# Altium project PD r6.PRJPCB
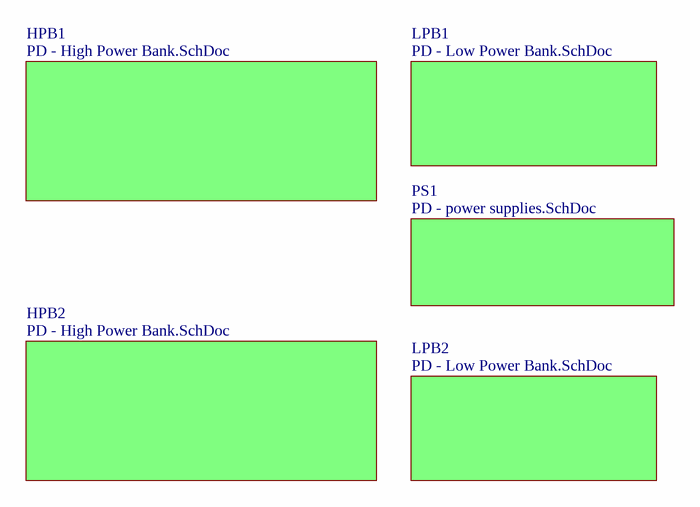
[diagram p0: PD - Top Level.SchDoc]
ProjectTitle: FRoSTY Power Distribution, Rev 6
8 sheets, 258 parts. Net scope: flat (ports and power ports of the same name join across sheets).
Board file: PD6.PcbDoc
Sheets:
  PD - Top Level.SchDoc
    PS1 = PD - power supplies.SchDoc
      U1000 = 24V_1.5A Supply.SchDoc
      U_5V_3A Supply = 5V_3A Supply.SchDoc
      U_12V_2A Supply = 12V_2A Supply.SchDoc
    HPB2 = PD - High Power Bank.SchDoc
    HPB1 = PD - High Power Bank.SchDoc
    LPB1 = PD - Low Power Bank.SchDoc
    LPB2 = PD - Low Power Bank.SchDoc
  Title.SchDoc

## Sheet PD - Top Level.SchDoc: Top Level
size Letter; DrawnBy: EJVW; Revision: 2

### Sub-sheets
HPB1 = PD - High Power Bank.SchDoc: no entries
HPB2 = PD - High Power Bank.SchDoc: no entries
LPB1 = PD - Low Power Bank.SchDoc: no entries
LPB2 = PD - Low Power Bank.SchDoc: no entries
PS1 = PD - power supplies.SchDoc: no entries

## Sheet PD - power supplies.SchDoc: Power Supplies
size Letter; DrawnBy: EJVW; DocumentNumber: 4; Revision: 4; SheetNumber: 3; SheetTotal: 6; PageSetup: Record=PageOptions|CenterHorizontal=True|CenterVertical=True|PrintScale=0.96|XCorrection=1.00|YCorrection=1.00|PrintKind=1|BorderSize=5000000|LeftOffset=0|BottomOffset=0|Orientation=2|PaperLength=1000|PaperWidth=1000|Scale=100|PaperSource=7|PrintQuality=-4|MediaType=1|DitherType=10|PaperKind=11x17|PrintScaleMode=1
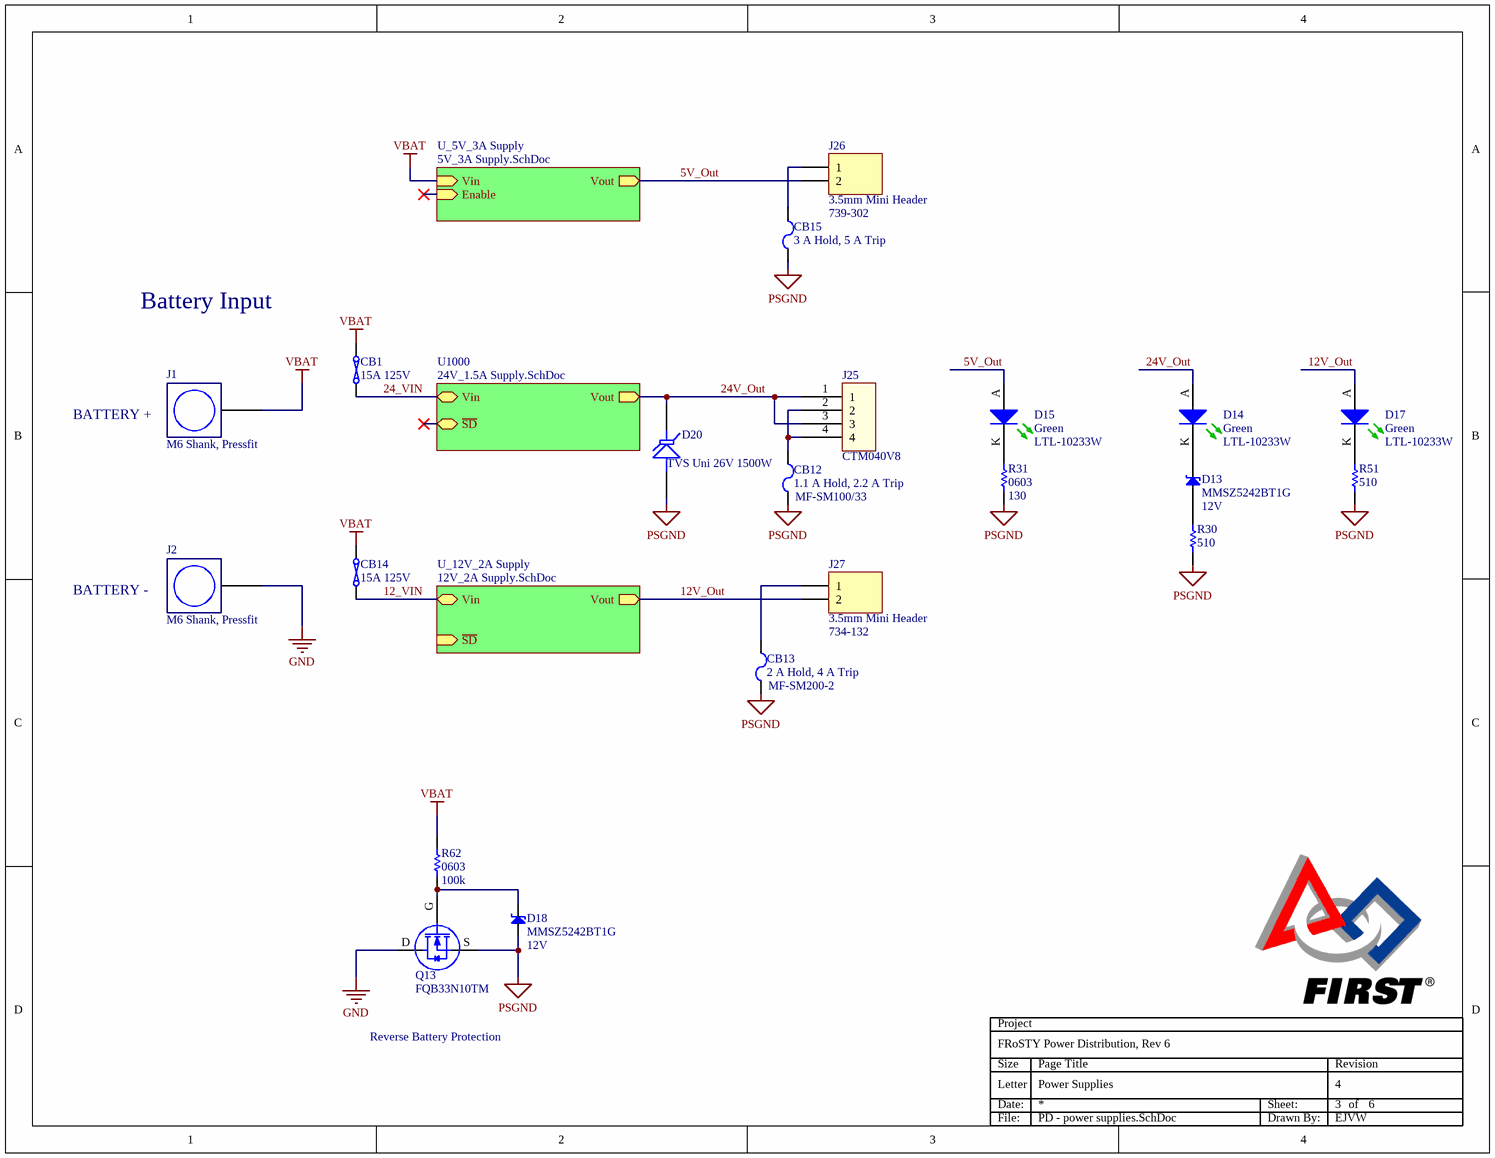
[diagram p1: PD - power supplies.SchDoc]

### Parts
(Parts that share a designator on the sheet are numbered #1, #2 ... from top to bottom, then left to right.)
CB1#1  15A 125V  [Fuse2410 - bel]
CB12#1  1.1 A Hold, 2.2 A Trip  [PTC-MF-SM-Small]
CB13#1  2 A Hold, 4 A Trip  [PTC-MF-SM-Large]
CB14#1  15A 125V  [Fuse2410 - bel]
CB15  3 A Hold, 5 A Trip  [2920L]
D13  MMSZ5242BT1G  value 12V  [SOD-123]
D14  Green  [T-1 3/4]
D15  Green  [T-1 3/4]
D17  Green  [T-1 3/4]
D18#1  MMSZ5242BT1G  value 12V  [SOD-123]
D20#1  TVS Uni 26V 1500W  [SMC]
J1#1  M6 Shank, Pressfit  [Wurth 7461098]
J2#1  M6 Shank, Pressfit  [Wurth 7461098]
J25  MFG_PN: CTM040V8  [Sauro CTM040V8]  (hidden comment: Sauro CTM040V8)
J26  3.5mm Mini Header  MFG_PN: 739-302  [WAGO 739-302]
J27  3.5mm Mini Header  MFG_PN: 734-132  [WAGO 734-132]
Q13  FQB33N10TM  [TO-263AB/D2PAK]
R30#1  value 510  [R1206_C]  (hidden comment: 510 ohm 1206 1%)
R31#1  value 130  Footprint: 0603  [R0603_C]  (hidden comment: 130 ohm 0603 1%)
R51#1  value 510  [R1206_C]  (hidden comment: 510 ohm 1206 1%)
R62#1  value 100k  Footprint: 0603  [R0603_C]  (hidden comment: 100k ohm 0603 1%)

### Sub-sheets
U1000 = 24V_1.5A Supply.SchDoc: Vout (out), ~{SD}, Vin
U_5V_3A Supply = 5V_3A Supply.SchDoc: Vin (in), Enable (in), Vout (out)
U_12V_2A Supply = 12V_2A Supply.SchDoc: Vout (out), ~{SD} (in), Vin

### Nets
GND: J2#1.PAD Q13.D
PSGND: CB12#1.1 CB13#1.1 CB15.1 D18#1.A D20#1.A Q13.S R30#1.1 R31#1.1 R51#1.1
VBAT: CB1#1.2 CB14#1.2 J1#1.PAD R62#1.2 ; sheet U_5V_3A Supply/Vin
5V_Out: D15.A J26.2 ; sheet U_5V_3A Supply/Vout
12_VIN: CB14#1.1 ; sheet U_12V_2A Supply/Vin
12V_Out: D17.A J27.2 ; sheet U_12V_2A Supply/Vout
24_VIN: CB1#1.1 ; sheet U1000/Vin
24V_Out: D14.A D20#1.K J25.1 J25.3 ; sheet U1000/Vout
NetCB12#1_2: CB12#1.2 J25.2 J25.4
NetCB13#1_2: CB13#1.2 J27.1
NetCB15_2: CB15.2 J26.1
NetD13_A: D13.A R30#1.2
NetD13_K: D13.K D14.K
NetD15_K: D15.K R31#1.2
NetD17_K: D17.K R51#1.2
NetD18#1_K: D18#1.K Q13.G R62#1.1

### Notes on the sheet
- Battery Input
- BATTERY +
- BATTERY -
- Reverse Battery Protection

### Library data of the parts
CB1#1 CB14#1 = Fuse SSQ 15: FUSE 12A 125V 6125 FAST SSQ; MFG: Bel Fuse Inc; MFG_PN: SSQ 15; DIST: DigiKey; DIST_PN: 507-1059-1-ND; R_min: 4; I trip (A): 15; Time to Trip: 10s @ 25A; V Max: 125; Cost (1000): 0.22400; Cost (MOQ): 0.76000
CB12#1 = MF-SM100/33: PTC 1.1A / 2.2A SMT; MFG: Bourns Inc.; DIST: DigiKey; DIST_PN: MF-SM100/33-2CT-ND; R_min: 120 mOhms; I hold (A): 2.2; I trip (A): 1.1; R_max: 410 mOhms; Time to Trip: 5 s @ 8 A; V Max: 33 V; I max (A): 40; Cost (1000): 0.40
CB13#1 = MF-SM200-2: PTC 2A /  4A SMT; MFG: Bourns Inc.; DIST: DigiKey; DIST_PN: MF-SM200CT-ND; R_min: 45; I hold (A): 2; I trip (A): 4; R_max: 125; Time to Trip: 12 s @ 8 A; V Max: 15; I max (A): 100; Cost (1000): 0.44650; Cost (MOQ): 0.67000
CB15 = 2920L300/15DR: PTC 3A /  5A SMT2920; MFG: LITTELFUSE; DIST: Newark; DIST_PN: 05M2801; R_min: 15 mOhms; I hold (A): 3.00; I trip (A): 5.00; R_max: 30 mOhms; Time to Trip: 10.3s @ 12.5A; V Max: 15; I max (A): 40.0; Cost (1000): 0.379; R post trip (1000): 48; Cost (MOQ): 0.500
D13 D18#1 = MMSZ5242BT1G_1: 12V 500mW Zener; MFG: ON Semiconductor; DIST: DIGIKEY; DIST_PN: MMSZ5242BT1GOSCT-ND; Checked: SCH 11/17/07
D14 D15 D17 = LTL-10233W: T-1 3/4 Green; DIST: DigiKey; DIST_PN: 160-1089-ND; MFG: LITE-ON INC; V_F: 2.1V; I_F: 20mA; Maximum Continuous Current: 30mA; Luminous Intensity: 40 mcd; Cost (1000): 0.04640; Cost (MOQ): 0.07300
D20#1 = SMCJ26A: Cost (1000): 0.32490; Cost (MOQ): 0.64000; DIST: DigiKey; DIST_PN: SMCJ26ALFCT-ND; MFG: Littelfuse Inc
J1#1 J2#1 = Wurth M6 PressFit Shank: MFG: Wurth Elektronik; MFG_PN: 7461098; Current Rating: 250 A; Cost (1000): 1.55; Cost (MOQ): 1.90
J25 = Sauro CTM040V8: 4 position, vertical locking connector with screw flanges, 3.5mm spacing; BOM Note: Specified by NI; Current Rating: 13.5; Engagement Force: 12 N (3 per Pole); Mates With: CTF04BV8-CN
J26 = WAGO 739-302: 3.5mm Terminal Strip, 14-28 AWG; MFG: WAGO; Current Rating: 6
J27 = WAGO 734-132: 3.5mm Header Protected against Mismating; MFG: WAGO; Checked: SCH 11/11/07; Current Rating: 10 A; Mates With: 734-102/037-000
Q13 = FQB33N10TM: N-CH 100V D2 33A; MFG: Fairchild; DIST: DigiKey; DIST_PN: FQB33N10TMCT-ND; R_DS: 52mOhms; V_DS: 100; V_GS: 25; R?JC: 50; Topology: N; Cost (1000): 0.48720; Cost (MOQ): 1.04000; Q_G (nC): 38; V_THRESH (Volts): 2 - - 4; ID @ TA = 25°C (Amps): 33; BOM Note: Or similar - VGS>=30V, I_D > 25 A
R30#1 R51#1 = 510 ohm 1206 1%: MFG: Rohm; MFG_PN: MCR18EZHF3300; DIST: DigiKey; DIST_PN: RHM510FRCT-ND; Power: 0.25W, 1/4W; Cost (1000): 0.02262
R31#1 = 130 ohm 0603 1%: MFG: Rohm; MFG_PN: MCR03EZPFX1300; DIST: DigiKey; DIST_PN: RHM130HCT-ND; Power: 0.1; BOM Note: Generic - May be replaced by equal or better part; Cost (1000): 0.01595; Cost (MOQ): 0.076
R62#1 = 100k ohm 0603 1%: MFG: Rohm; MFG_PN: MCR03EZPFX1003; DIST: DigiKey; DIST_PN: RHM100KHCT-ND; Power: 0.1; Cost (1000): 0.01595; Cost (MOQ): 0.076; BOM Note: Generic - May be replaced by equal or better part

## Sheet 24V_1.5A Supply.SchDoc: 24V 1A Boost Supply, 4.5-15V Input
size Letter; DrawnBy: EJVW; DocumentNumber: 6; Revision: 4; SheetNumber: 6; SheetTotal: 6
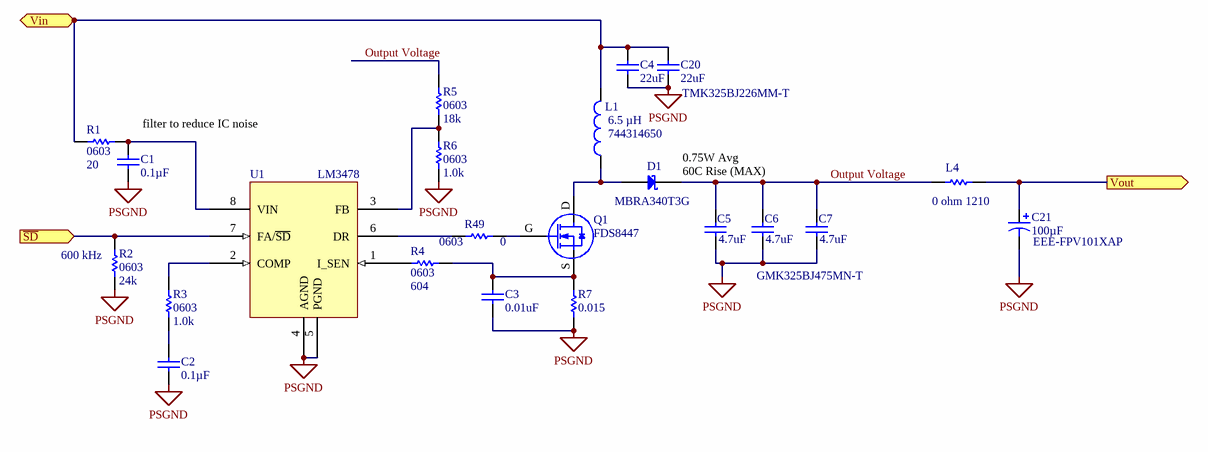
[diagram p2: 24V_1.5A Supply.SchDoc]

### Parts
(Parts that share a designator on the sheet are numbered #1, #2 ... from top to bottom, then left to right.)
C1  value 0.1µF  [C0805_C]  (hidden comment: 0.1uF 0805 Bypass)
C2  value 0.1µF  [C0805_C]  (hidden comment: 0.1uF 0805 Bypass)
C3  value 0.01uF  [C0603_C]  (hidden comment: 0.01uF 0603)
C4  value 22uF  [C1210_C]  (hidden comment: 22uF 1210 High I_RMS)
C5  value 4.7uF  [C1210_C]  (hidden comment: 4.7uF 1210 High I_RMS)
C6  value 4.7uF  [C1210_C]  (hidden comment: 4.7uF 1210 High I_RMS)
C7  value 4.7uF  MFG_PN: GMK325BJ475MN-T  [C1210_C]  (hidden comment: 4.7uF 1210 High I_RMS)
C20  value 22uF  MFG_PN: TMK325BJ226MM-T  [C1210_C]  (hidden comment: 22uF 1210 High I_RMS)
C21  value 100µF  MFG_PN: EEE-FPV101XAP  [SMT-CAN Panasonic D8]  (hidden comment: 100µF SMT - Panasonic)
D1#1  MBRA340T3G  [SMA]
L1  value 6.5 µH  MFG_PN: 744314650  [Wurth WE-HC 744314X]  (hidden comment: 4.7 µH 6 A)
L4  0 ohm 1210  [R1210_C]
Q1#1  FDS8447  [SO-8_M FET]
R1#1  value 20  Footprint: 0603  [R0603_C]  (hidden comment: 20 ohm 0603 1%)
R2#1  value 24k  Footprint: 0603  [R0603_C]  (hidden comment: 24k ohm 0603 1%)
R3#1  value 1.0k  Footprint: 0603  [R0603_C]  (hidden comment: 1.0k ohm 0603 1%)
R4#1  value 604  Footprint: 0603  [R0603_C]  (hidden comment: 604 ohm 0603 1%)
R5#1  value 18k  Footprint: 0603  [R0603_C]  (hidden comment: 18k ohm 0603 1%)
R6#1  value 1.0k  Footprint: 0603  [R0603_C]  (hidden comment: 1.0k ohm 0603 1%)
R7#1  value 0.015  [RL3720 - Susumu]  (hidden comment: 15 milliohm RL3720 2% 1W)
R49  value 0  Footprint: 0603  [R0603_C]  (hidden comment: 0 ohm 0603)
U1  LM3478  [MUA08A]

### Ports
Vin (in), Vout (out), ~{SD} (in)

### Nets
PSGND: C1.1 C2.1 C3.1 C4.1 C5.1 C6.1 C7.1 C20.1 C21.- R2#1.1 R6#1.1 R7#1.1 U1.4(AGND) U1.5(PGND)
Output Voltage: C5.2 C6.2 C7.2 D1#1.K L4.1 R5#1.2
NetC1_2: C1.2 R1#1.2 U1.8(VIN)
NetC2_2: C2.2 R3#1.1
NetC3_2: C3.2 Q1#1.S R4#1.2 R7#1.2
NetC4_2: C4.2 C20.2 L1.2 R1#1.1 ; port Vin
NetC11_2: C21.+ L4.2 ; port Vout
NetD1#1_A: D1#1.A L1.1 Q1#1.D
NetQ1#1_G: Q1#1.G R49.2
NetR2#1_2: R2#1.2 U1.7(FA/~{SD}) ; port ~{SD}
NetR3#1_2: R3#1.2 U1.2(COMP)
NetR4#1_1: R4#1.1 U1.1(I_SEN)
NetR5#1_1: R5#1.1 R6#1.2 U1.3(FB)
NetR49_1: R49.1 U1.6(DR)

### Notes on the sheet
- filter to reduce IC noise
- (near D1#1) 0.75W Avg
  60C Rise (MAX)
- (near R2#1) 600 kHz

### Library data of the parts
C1 C2 = 0.1uF 0805 Bypass: MFG: Kemet; MFG_PN: C0805C104K5RACTU; DIST: DigiKey; DIST_PN: 399-1170-1-ND; Tolerance: ±10%; Temperature Coefficient: X7R; Voltage: 50; Checked: SCH 3/2/2008; Cost (1000): 0.01260
C3 = 0.01 uF 0603 50V: MFG: Kemet; MFG_PN: C0603C103K5RACTU; DIST: DigiKey; DIST_PN: 399-1091-1-ND; Tolerance: ±10%; Temperature Coefficient: X7R; Voltage: 50V; Checked: SCH 3/2/2008; Cost (1000): 0.00520; Cost (MOQ): 0.02200
C4 = 22uF 1210 25V X5R: MFG: Taiyo Yuden; MFG_PN: TMK325BJ226MM-T; DIST: DigiKey; DIST_PN: 587-2086-1-ND; Tolerance: 20%; Voltage: 25; I_RMS@1000KHz Max: 4.4; I_RMS@10KHz Max: 2.6; ESR: .005; Cost (1000): 0.26600; Cost (MOQ): 1.62800
C5 C6 = 4.7uF 1210 High I_RMS: 4.7uF 1210 35V X5R; MFG: Taiyo Yuden; MFG_PN: GMK325BJ475MN-T; DIST: DigiKey; DIST_PN: 587-1781-1-ND; Tolerance: 20%; Voltage: 35; I_RMS@10KHz Max: 1.5A; I_RMS@100kHz Max: 3.5A
C7 = 4.7uF 1210 High I_RMS: 4.7uF 1210 35V X5R; MFG: Taiyo Yuden; DIST: DigiKey; DIST_PN: 587-1781-1-ND; Tolerance: 20%; Voltage: 35; I_RMS@10KHz Max: 1.5A; I_RMS@100kHz Max: 3.5A
C20 = 22uF 1210 25V X5R: MFG: Taiyo Yuden; DIST: DigiKey; DIST_PN: 587-2086-1-ND; Tolerance: 20%; Voltage: 25; I_RMS@1000KHz Max: 4.4; I_RMS@10KHz Max: 2.6; ESR: .005; Cost (1000): 0.26600; Cost (MOQ): 1.62800
C21 = 100µF 35V EEEFPV101XAP: 100µF 35V CAN-SMT; DIST: DigiKey; DIST_PN: PCE4554CT-ND; MFG: Panasonic - ECG; Tolerance: ±20%; Voltage: 35; Max Temperature: 105C; ESR: .160; Cost (1000): 0.36100; Cost (MOQ): 0.61400
D1#1 = MBRA340T3G: 3A Schottky Diode; DIST: DigiKey; DIST_PN: MBRA340T3GOSCT-ND; MFG: ON Semiconductor; Forward Voltage: 0.38; Surge Rating (8.3ms Half Sine): 100A; Voltage Rating: 40V
L1 = WE-HC 6.5-6: 6.5 µH 6 A 20% SMD; MFG: Wurth; DIST: DigiKey; DIST_PN: 732-1162-1-ND; Cost (1000): 1.10000; DCR (Ohms): .025; Cost (MOQ): 3.30000; IRMS (40C) A: 5.9; ISAT (10%)  A: 3; SRF (MHz): 50
L4 = 0 ohm 1210 5%: MFG: Vishay/Dale; MFG_PN: CRCW12100000Z0EA; DIST: DigiKey; DIST_PN: 541-0.0VCT-ND; Cost (1000): 0.05510; Cost (MOQ): 0.26100; Value: 0; Power: 0.333W, 1/3W
Q1#1 = FDS8447: N-CH 40V SO8 12.8A; MFG: Fairchild; DIST: DigiKey; DIST_PN: FDS8447CT-ND; Q_G (nC): 35; R_DS: 10.5mOhms; V_DS: 40; V_GS: 20; ID @ TA = 25°C (Amps): 12.8; R?JC: 50; Topology: N; V_THRESH (Volts): 1 - 1.8 - 3; Cost (1000): 0.41895
R1#1 = 20 ohm 0603 1%: MFG: Rohm; MFG_PN: MCR03EZPFX20R0; DIST: DigiKey; DIST_PN: RHM20.0HCT-ND; Power: 0.1; BOM Note: Generic - May be replaced by equal or better part; Cost (1000): 0.01595; Cost (MOQ): 0.076
R2#1 = 24k ohm 0603 1%: MFG: Rohm; MFG_PN: MCR03EZPFX2402; DIST: DigiKey; DIST_PN: RHM24.0KHCT-ND; Power: 0.1; BOM Note: Generic - May be replaced by equal or better part; Cost (1000): 0.01595; Cost (MOQ): 0.076
R3#1 R6#1 = 1.0k ohm 0603 1%: MFG: Rohm; MFG_PN: MCR03EZPFX1001; DIST: DigiKey; DIST_PN: RHM1.00KHCT-ND; Power: 0.1; BOM Note: Generic - May be replaced by equal or better part; Cost (1000): 0.01595; Cost (MOQ): 0.076
R4#1 = 604 ohm 0603 1%: MFG: Rohm; MFG_PN: MCR03EZPFX6040; DIST: DigiKey; DIST_PN: RHM604HCT-ND; Power: 0.1 W
R5#1 = 18k ohm 0603 1%: MFG: Rohm; MFG_PN: MCR03EZPFX1802; DIST: DigiKey; DIST_PN: RHM18.0KHCT-ND; Power: 0.1; BOM Note: Generic - May be replaced by equal or better part; Cost (1000): 0.01595; Cost (MOQ): 0.076
R7#1 = 15 milliohm RL3720 2% 1W: MFG: Susumu Co Ltd; MFG_PN: RL3720WT-R015-G; DIST: DigiKey; DIST_PN: RL37WT.015GCT-ND; Power: 0.5; Cost (1000): 0.348; Cost (MOQ): 1.65
R49 = 0 ohm 0603: MFG: Rohm; MFG_PN: MCR03EZPJ000; DIST: DigiKey; DIST_PN: RHM0.0GCT-ND; Power: 0.1; Cost (1000): 0.01595; Cost (MOQ): 0.076; BOM Note: Generic - May be replaced by equal or better part
U1 = LM3478: Low Side N Switcher Controller - Boost, Flyback, SEPIC; DIST: DigiKey; DIST_PN: LM3478MMCT-ND; MFG: National; MFG_PN: LM3478MM/NOPB; ADJ Pin Voltage: 1.26 V; Checked: SCH 3/2/2008; Current Limit: "10 A"; Driver Current Limit: 1 A; Max Voltage: 40 V; Quiescent Current: 2 mA; Shutdown Current: 2 uA; Voltage Output: Adj

## Sheet 5V_3A Supply.SchDoc: 5V 3A Buck Supply, 7-15V Input
size Letter; DrawnBy: EJVW; Revision: 1
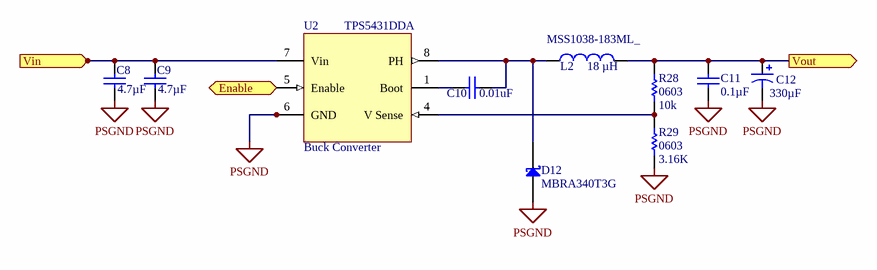
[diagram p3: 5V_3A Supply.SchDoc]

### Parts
(Parts that share a designator on the sheet are numbered #1, #2 ... from top to bottom, then left to right.)
C8  value 4.7µF  [C0805_C]  (hidden comment: 4.7uF 0805 25V X5R)
C9  value 4.7µF  [C0805_C]  (hidden comment: 4.7uF 0805 25V X5R)
C10  value 0.01uF  [C0603_C]  (hidden comment: 0.01uF 0603)
C11  value 0.1µF  [C0805_C]  (hidden comment: 0.1uF 0805 Bypass)
C12  value 330µF  [SMT-CAN Nippon F80]  (hidden comment: 330µF SMT - Chemi-Con)
D12  MBRA340T3G  [SMA]
L2  value 18 µH  [CoilCraft MSS1038]  (hidden comment: 18 µH 3.35A ±20% SMD)
R28#1  value 10k  Footprint: 0603  [R0603_C]  (hidden comment: 10k ohm 0603 1%)
R29#1  value 3.16K  Footprint: 0603  [R0603_C]  (hidden comment: 3.16k ohm 0603 1%)
U2  Buck Converter  MFG_PN: TPS5431DDA  [TPS543X]

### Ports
Enable (in), Vin (in), Vout (out)

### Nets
PSGND: C8.1 C9.1 C11.1 C12.- D12.A R29#1.1 U2.6(GND) U2.PAD
NetC4_2: C8.2 C9.2 U2.7(Vin) ; port Vin
NetC10_1: C10.1 U2.1(Boot)
NetC10_2: C10.2 D12.K L2.1 U2.8(PH)
NetC11_2: C11.2 C12.+ L2.2 R28#1.2 ; port Vout
NetR28#1_1: R28#1.1 R29#1.2 U2.4(V_Sense)
NetU2_5: U2.5(Enable) ; port Enable

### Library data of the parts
C8 C9 = 4.7uF 0805 25V X5R: CERAMIC 4.7uF 25V X5R 0805; MFG: Panasonic - ECG; MFG_PN: ECJ-2FB1E475M; DIST: DigiKey; DIST_PN: PCC2321CT-ND; Tolerance: ±20%; Checked: SCH 3/2/2008; Cost (1000): 0.08988
C10 = 0.01 uF 0603 50V: as C3 on sheet 24V_1.5A Supply
C11 = 0.1uF 0805 Bypass: as C1 on sheet 24V_1.5A Supply
C12 = 330µF 6.3V CAN-SMT: 330µF 6.3V ELECT CAN-SMT; DIST: DigiKey; DIST_PN: 565-2059-1-ND; MFG: United Chemi-Con; MFG_PN: EMVA6R3ADA331MF80G; Tolerance: ±20%; Checked: SCH 3/2/2008; Max Temperature: 85 C; Ripple Current: 0.135 A; Cost (1000): 0.10266
D12 = MBRA340T3G: as D1#1 on sheet 24V_1.5A Supply
L2 = MSS1038-183ML_: MFG: CoilCraft; DCR (Ohms): 0.065; IRMS (20C) A: 2.25; IRMS (40C) A: 3.35; ISAT (10%)  A: 2.44; ISAT (20%) A: 3.1; ISAT (30%) A: 3.52; SRF (MHz): 18; Cost (1000): 0.41
R28#1 = 10k ohm 0603 1%: MFG: Rohm; MFG_PN: MCR03EZPFX1002; DIST: DigiKey; DIST_PN: RHM10.0KHCT-ND; Power: 0.1; BOM Note: Generic - May be replaced by equal or better part; Cost (1000): 0.01595; Cost (MOQ): 0.076
R29#1 = 3.16k ohm 0603 1%: MFG: Rohm; MFG_PN: MCR03EZPFX3161; DIST: DigiKey; DIST_PN: RHM3.16KHCT-ND; Power: 0.1 W
U2 = TPS5431: 3-A, WIDE INPUT RANGE, STEP-DOWN SWIFT CONVERTER; ADJ Pin Voltage: 1.221; Checked: SCH 3/2/2008; Current Limit: 3; DIST: DigiKey; DIST_PN: 296-19662-5-ND; Max Voltage: 23; MFG: TI; Quiescent Current: 3 mA; Shutdown Current: 20 uA; Voltage Output: 1.22 +; Switch Frequency (kHz): 500; Cost (1000): 2.20; BOM Note: May be replaced by TPS5430

## Sheet 12V_2A Supply.SchDoc: 12V 2A Boost Supply, 4.5-12V Input
size Letter; DrawnBy: EJVW; DocumentNumber: 5; Revision: 2; SheetNumber: 5; SheetTotal: 6
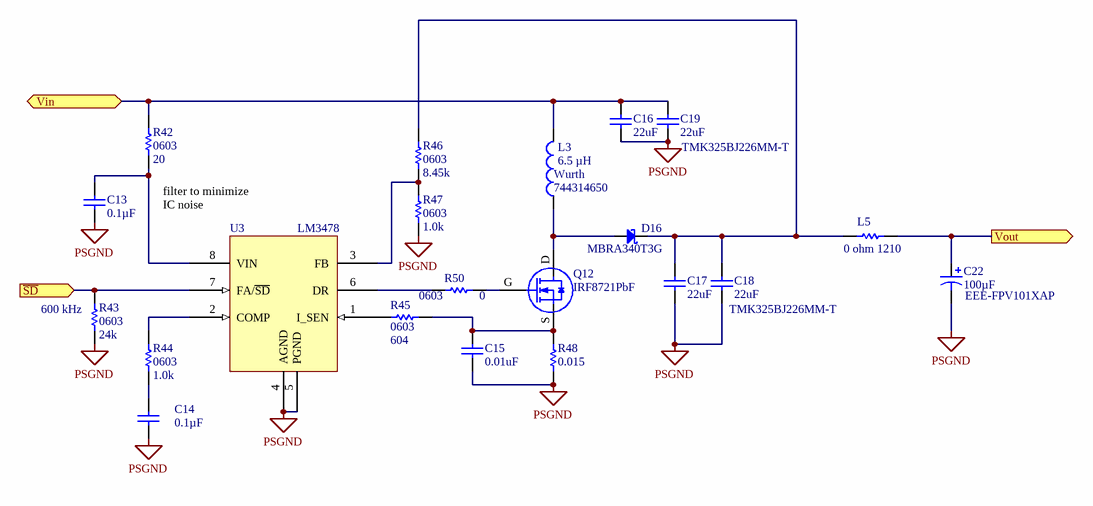
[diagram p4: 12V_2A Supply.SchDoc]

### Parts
C13  value 0.1µF  [C0805_C]  (hidden comment: 0.1uF 0805 Bypass)
C14  value 0.1µF  [C0805_C]  (hidden comment: 0.1uF 0805 Bypass)
C15  value 0.01uF  [C0603_C]  (hidden comment: 0.01uF 0603)
C16  value 22uF  [C1210_C]  (hidden comment: 22uF 1210 High I_RMS)
C17  value 22uF  [C1210_C]  (hidden comment: 22uF 1210 High I_RMS)
C18  value 22uF  MFG_PN: TMK325BJ226MM-T  [C1210_C]  (hidden comment: 22uF 1210 High I_RMS)
C19  value 22uF  MFG_PN: TMK325BJ226MM-T  [C1210_C]  (hidden comment: 22uF 1210 High I_RMS)
C22  value 100µF  MFG_PN: EEE-FPV101XAP  [SMT-CAN Panasonic D8]  (hidden comment: 100µF SMT - Panasonic)
D16  MBRA340T3G  [SMA]
L3  value 6.5 µH  MFG: Wurth  MFG_PN: 744314650  [Wurth WE-HC 744314X]  (hidden comment: 4.7 µH 6 A)
L5  0 ohm 1210  [R1210_C]
Q12  IRF8721PbF  [SO-8_M FET]
R42  value 20  Footprint: 0603  [R0603_C]  (hidden comment: 20 ohm 0603 1%)
R43  value 24k  Footprint: 0603  [R0603_C]  (hidden comment: 24k ohm 0603 1%)
R44  value 1.0k  Footprint: 0603  [R0603_C]  (hidden comment: 1.0k ohm 0603 1%)
R45  value 604  Footprint: 0603  [R0603_C]  (hidden comment: 604 ohm 0603 1%)
R46  value 8.45k  Footprint: 0603  [R0603_C]  (hidden comment: 8.45k ohm 0603 1%)
R47  value 1.0k  Footprint: 0603  [R0603_C]  (hidden comment: 1.0k ohm 0603 1%)
R48  value 0.015  [RL3720 - Susumu]  (hidden comment: 15 milliohm RL3720 2% 1W)
R50  value 0  Footprint: 0603  [R0603_C]  (hidden comment: 0 ohm 0603)
U3  LM3478  [MUA08A]

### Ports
Vin, Vout (out), ~{SD} (in)

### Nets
PSGND: C13.1 C14.1 C15.1 C16.1 C17.1 C18.1 C19.1 C22.- R43.1 R47.1 R48.1 U3.4(AGND) U3.5(PGND)
NetC4_2: C16.2 C19.2 L3.2 R42.2 ; port Vin
NetC11_2: C22.+ L5.2 ; port Vout
NetC13_2: C13.2 R42.1 U3.8(VIN)
NetC14_2: C14.2 R44.1
NetC15_2: C15.2 Q12.S R45.2 R48.2
NetC17_2: C17.2 C18.2 D16.K L5.1 R46.2
NetD16_A: D16.A L3.1 Q12.D
NetQ12_G: Q12.G R50.2
NetR2#1_2: R43.2 U3.7(FA/~{SD}) ; port ~{SD}
NetR44_2: R44.2 U3.2(COMP)
NetR45_1: R45.1 U3.1(I_SEN)
NetR46_1: R46.1 R47.2 U3.3(FB)
NetR50_1: R50.1 U3.6(DR)

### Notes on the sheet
- (near R42) filter to minimize IC noise
- (near R43) 600 kHz

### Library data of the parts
C13 = 0.1uF 0805 Bypass: as C1 on sheet 24V_1.5A Supply
C14 = 0.1uF 0805 Bypass: DIST: DigiKey; DIST_PN: 399-1170-1-ND; Tolerance: ±10%; Temperature Coefficient: X7R; MFG: Kemet; MFG_PN: C0805C104K5RACTU; Voltage: 50; Checked: SCH 3/2/2008; Cost (1000): 0.01260
C15 = 0.01 uF 0603 50V: as C3 on sheet 24V_1.5A Supply
C16 = 22uF 1210 25V X5R: as C4 on sheet 24V_1.5A Supply
C17 = 22uF 1210 25V X5R: MFG: Taiyo Yuden; MFG_PN: TMK325BJ226MM-T; DIST: DigiKey; DIST_PN: 587-2086-1-ND; Tolerance: 20%; Voltage: 25; ESR: .005; Cost (1000): 0.26600; I_RMS@10KHz Max: 2.6; I_RMS@100kHz Max: 4.4; Cost (MOQ): 1.62800
C18 = 22uF 1210 25V X5R: MFG: Taiyo Yuden; DIST: DigiKey; DIST_PN: 587-2086-1-ND; Tolerance: 20%; Voltage: 25; ESR: .005; Cost (1000): 0.26600; I_RMS@10KHz Max: 2.6; I_RMS@100kHz Max: 4.4; Cost (MOQ): 1.62800
C19 = 22uF 1210 25V X5R: as C20 on sheet 24V_1.5A Supply
C22 = 100µF 35V EEEFPV101XAP: as C21 on sheet 24V_1.5A Supply
D16 = MBRA340T3G: as D1#1 on sheet 24V_1.5A Supply
L3 = WE-HC 6.5-6: 6.5 µH 6 A 20% SMD; DIST: DigiKey; DIST_PN: 732-1162-1-ND; DCR (Ohms): .025; IRMS (40C) A: 5.9; ISAT (10%)  A: 3; SRF (MHz): 50; Cost (1000): 1.10000; Cost (MOQ): 3.30000
L5 = 0 ohm 1210 5%: as L4 on sheet 24V_1.5A Supply
Q12 = IRF8721PbF: N-CH 30V 8SOIC; MFG: IRF; DIST: Arrow; Q_G (nC): 8.3; R_DS: 8.5mOhms; V_GS: 20; ID @ TA = 25°C (Amps): 14; R?JC: 50; Topology: N; V_THRESH (Volts): 1.35 - 2.35; ID @ TA = 70°C (Amps): 11; Cost (1000): 0.229
R42 = 20 ohm 0603 1%: MFG: Rohm; MFG_PN: MCR03EZPFX20R0; DIST: DigiKey; DIST_PN: RHM20.0HCT-ND; Power: 0.1 W
R43 = 24k ohm 0603 1%: MFG: Rohm; MFG_PN: MCR03EZPFX2402; DIST: DigiKey; DIST_PN: RHM24.0KHCT-ND; Power: 0.1 W
R44 R47 = 1.0k ohm 0603 1%: MFG: Rohm; MFG_PN: MCR03EZPFX1001; DIST: DigiKey; DIST_PN: RHM1.00KHCT-ND; Power: 0.1 W
R45 = 604 ohm 0603 1%: as R4#1 on sheet 24V_1.5A Supply
R46 = 8.45k ohm 0603 1%: MFG: Panasonic - ECG; MFG_PN: ERJ-3EKF8451V; DIST: DigiKey; DIST_PN: P8.45KHCT-ND; Power: 0.1 W; Cost (1000): 0.01537; Cost (MOQ): 0.07300; BOM Note: Generic Part
R48 = 15 milliohm RL3720 2% 1W: as R7#1 on sheet 24V_1.5A Supply
R50 = 0 ohm 0603: as R49 on sheet 24V_1.5A Supply
U3 = LM3478: SEPIC Controller; DIST: DigiKey; DIST_PN: LM3478MMCT-ND; MFG: National; MFG_PN: LM3478MM/NOPB

## Sheet PD - High Power Bank.SchDoc: High Power Bank
size Letter; DrawnBy: EJVW; Revision: 2
Used 2 times, as channels HPB2, HPB1. Parts and nets are listed once, with the designators drawn on the sheet.
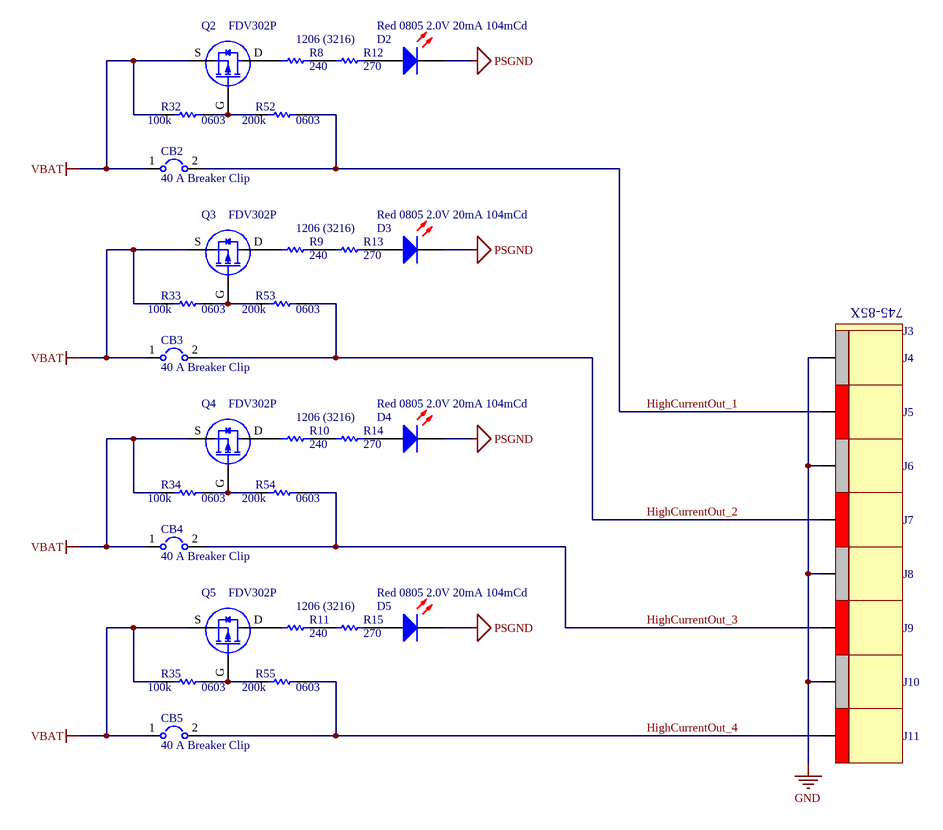
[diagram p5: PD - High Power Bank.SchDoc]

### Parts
CB2  40 A Breaker Clip  [Keystone 3555-2]
CB3  40 A Breaker Clip  [Keystone 3555-2]
CB4  40 A Breaker Clip  [Keystone 3555-2]
CB5  40 A Breaker Clip  [Keystone 3555-2]
D2  Red 0805 2.0V 20mA 104mCd  [LED_0805 0.8 Red]
D3  Red 0805 2.0V 20mA 104mCd  [LED_0805 0.8 Red]
D4  Red 0805 2.0V 20mA 104mCd  [LED_0805 0.8 Red]
D5  Red 0805 2.0V 20mA 104mCd  [LED_0805 0.8 Red]
J3  745-851  [WAGO 745-500]  (value not drawn)
J4  745-851  [WAGO 745-85X]  (value not drawn)
J5  745-85X Red  [WAGO 745-85X RED]  (value not drawn)
J6  745-851  [WAGO 745-85X]  (value not drawn)
J7  745-85X Red  [WAGO 745-85X RED]  (value not drawn)
J8  745-851  [WAGO 745-85X]  (value not drawn)
J9  745-85X Red  [WAGO 745-85X RED]  (value not drawn)
J10  745-851  [WAGO 745-85X]  (value not drawn)
J11  745-85X Red  [WAGO 745-85X RED]  (value not drawn)
Q2  FDV302P  [SOT-23 FET]
Q3  FDV302P  [SOT-23 FET]
Q4  FDV302P  [SOT-23 FET]
Q5  FDV302P  [SOT-23 FET]
R8  value 240  Footprint: 1206 (3216)  [R1206_C]  (hidden comment: 240 ohm 1206 5%)
R9  value 240  Footprint: 1206 (3216)  [R1206_C]  (hidden comment: 240 ohm 1206 5%)
R10  value 240  Footprint: 1206 (3216)  [R1206_C]  (hidden comment: 240 ohm 1206 5%)
R11  value 240  Footprint: 1206 (3216)  [R1206_C]  (hidden comment: 240 ohm 1206 5%)
R12  value 270  [R1206_C]  (hidden comment: 270 ohm 1206 5%)
R13  value 270  [R1206_C]  (hidden comment: 270 ohm 1206 5%)
R14  value 270  [R1206_C]  (hidden comment: 270 ohm 1206 5%)
R15  value 270  [R1206_C]  (hidden comment: 270 ohm 1206 5%)
R32  value 100k  Footprint: 0603  [R0603_C]  (hidden comment: 100k ohm 0603 1%)
R33  value 100k  Footprint: 0603  [R0603_C]  (hidden comment: 100k ohm 0603 1%)
R34  value 100k  Footprint: 0603  [R0603_C]  (hidden comment: 100k ohm 0603 1%)
R35  value 100k  Footprint: 0603  [R0603_C]  (hidden comment: 100k ohm 0603 1%)
R52  value 200k  Footprint: 0603  [R0603_C]  (hidden comment: 200k ohm 0603 1%)
R53  value 200k  Footprint: 0603  [R0603_C]  (hidden comment: 200k ohm 0603 1%)
R54  value 200k  Footprint: 0603  [R0603_C]  (hidden comment: 200k ohm 0603 1%)
R55  value 200k  Footprint: 0603  [R0603_C]  (hidden comment: 200k ohm 0603 1%)

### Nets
GND: J4.1 J6.1 J8.1 J10.1
PSGND: D2.K D3.K D4.K D5.K
VBAT: CB2.1 CB3.1 CB4.1 CB5.1 Q2.S Q3.S Q4.S Q5.S R32.1 R33.1 R34.1 R35.1
HighCurrentOut_1: CB2.2 J5.1 R52.2
HighCurrentOut_2: CB3.2 J7.1 R53.2
HighCurrentOut_3: CB4.2 J9.1 R54.2
HighCurrentOut_4: CB5.2 J11.1 R55.2
NetD2_A: D2.A R12.2
NetD3_A: D3.A R13.2
NetD4_A: D4.A R14.2
NetD5_A: D5.A R15.2
NetQ2_D: Q2.D R8.1
NetQ2_G: Q2.G R32.2 R52.1
NetQ3_D: Q3.D R9.1
NetQ3_G: Q3.G R33.2 R53.1
NetQ4_D: Q4.D R10.1
NetQ4_G: Q4.G R34.2 R54.1
NetQ5_D: Q5.D R11.1
NetQ5_G: Q5.G R35.2 R55.1
NetR8_2: R8.2 R12.1
NetR9_2: R9.2 R13.1
NetR10_2: R10.2 R14.1
NetR11_2: R11.2 R15.1

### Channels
HPB2: designators CB2=CB13#2 CB3=CB11 CB4=CB9 CB5=CB7 D2=D21 D3=D20#2 D4=D19 D5=D18#2 J3=J36 J4=J35 J5=J34 J6=J33 J7=J32 J8=J31 J9=J30 J10=J29 J11=J28 Q2=Q23 Q3=Q22 Q4=Q21 Q5=Q20 R8=R69 R9=R67 R10=R65 R11=R63 R12=R68 R13=R66 R14=R64 R15=R62#2 R32=R54 R33=R53 R34=R52 R35=R51#2 R52=R86 R53=R87 R54=R88 R55=R89
HPB1: designators CB2=CB8 CB3=CB10 CB4=CB12#2 CB5=CB14#2 D2=D1#2 D3=D2 D4=D3 D5=D4 J3=J2#2 J4=J1#2 J5=J3 J6=J4 J7=J5 J8=J6 J9=J7 J10=J8 J11=J9 Q2=Q1#2 Q3=Q2 Q4=Q3 Q5=Q4 R8=R1#2 R9=R3#2 R10=R5#2 R11=R7#2 R12=R2#2 R13=R4#2 R14=R6#2 R15=R8 R32=R22 R33=R23 R34=R24 R35=R25 R52=R82 R53=R83 R54=R84 R55=R85

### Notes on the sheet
- (near J3) 745-85X

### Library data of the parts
CB2-CB5 = KeyElco 3555-2: "MAXI" Automotive Fuse Clip and Holder; MFG: Keystone Electronics; MFG_PN: 3555-2; I hold (A): Per Breaker; I max (A): 60 A
D2-D5 = LS R976-NR-1-0-20-R18: DIST: DigiKey; DIST_PN: 475-1278-1-ND; MFG: OSRAM Opto Semiconductors Inc; V_F: 2.0; Maximum Continuous Current: 30 mA; Viewing Angle: 160; Cost (1000): 0.03800; Cost (MOQ): 0.07000
J3 = Wago 745-500: Wago 745-85X End Plate
J4 J6 J8 J10 = Wago 745-85X Grey: Current Rating: 76 A; MFG_PN: 745-851/006-000
J5 J7 J9 J11 = Wago 745-85X Red: Current Rating: 76 A
Q2-Q5 = FDV302P: P-Channel ESD-Protected MOSFET, -25V, 130mA, 5 Ohm; MFG: Fairchild Semiconductor; DIST: DigiKey; DIST_PN: FDV302PCT-ND; R_DS: 10000; V_DS: -25; V_GS: -8; I_D Continuous: -0.120; Topology: P; Cost (1000): 0.06380; Cost (MOQ): 0.29000; V_THRESH (Volts): -1; V_THRESH_MIN (V): -0.65; V_THRESH_MAX (V): -1.5; R?JA: 357
R8-R11 = 240 ohm 1206 5%: MFG: Rohm; MFG_PN: MCR18EZPJ241; DIST: DigiKey; DIST_PN: RHM240ERCT-ND; Power: 0.25W, 1/4W; Cost (1000): 0.01929
R12-R15 = 270 ohm 1206 5%: MFG: Rohm; MFG_PN: MCR18EZPJ271; DIST: DigiKey; DIST_PN: RHM270ERCT-ND; Power: 0.25W, 1/4W; Cost (1000): 0.01929
R32-R35 = 100k ohm 0603 1%: as R62#1 on sheet PD - power supplies
R52-R55 = 200k ohm 0603 1%: MFG: Rohm; MFG_PN: MCR03EZPFX2003; DIST: DigiKey; DIST_PN: RHM200KHCT-ND; Power: 0.1; Cost (1000): 0.01595; Cost (MOQ): 0.076; BOM Note: Generic - May be replaced by equal or better part

## Sheet PD - Low Power Bank.SchDoc: Low Power Bank
size Letter; DrawnBy: EJVW; Revision: 3
Used 2 times, as channels LPB1, LPB2. Parts and nets are listed once, with the designators drawn on the sheet.
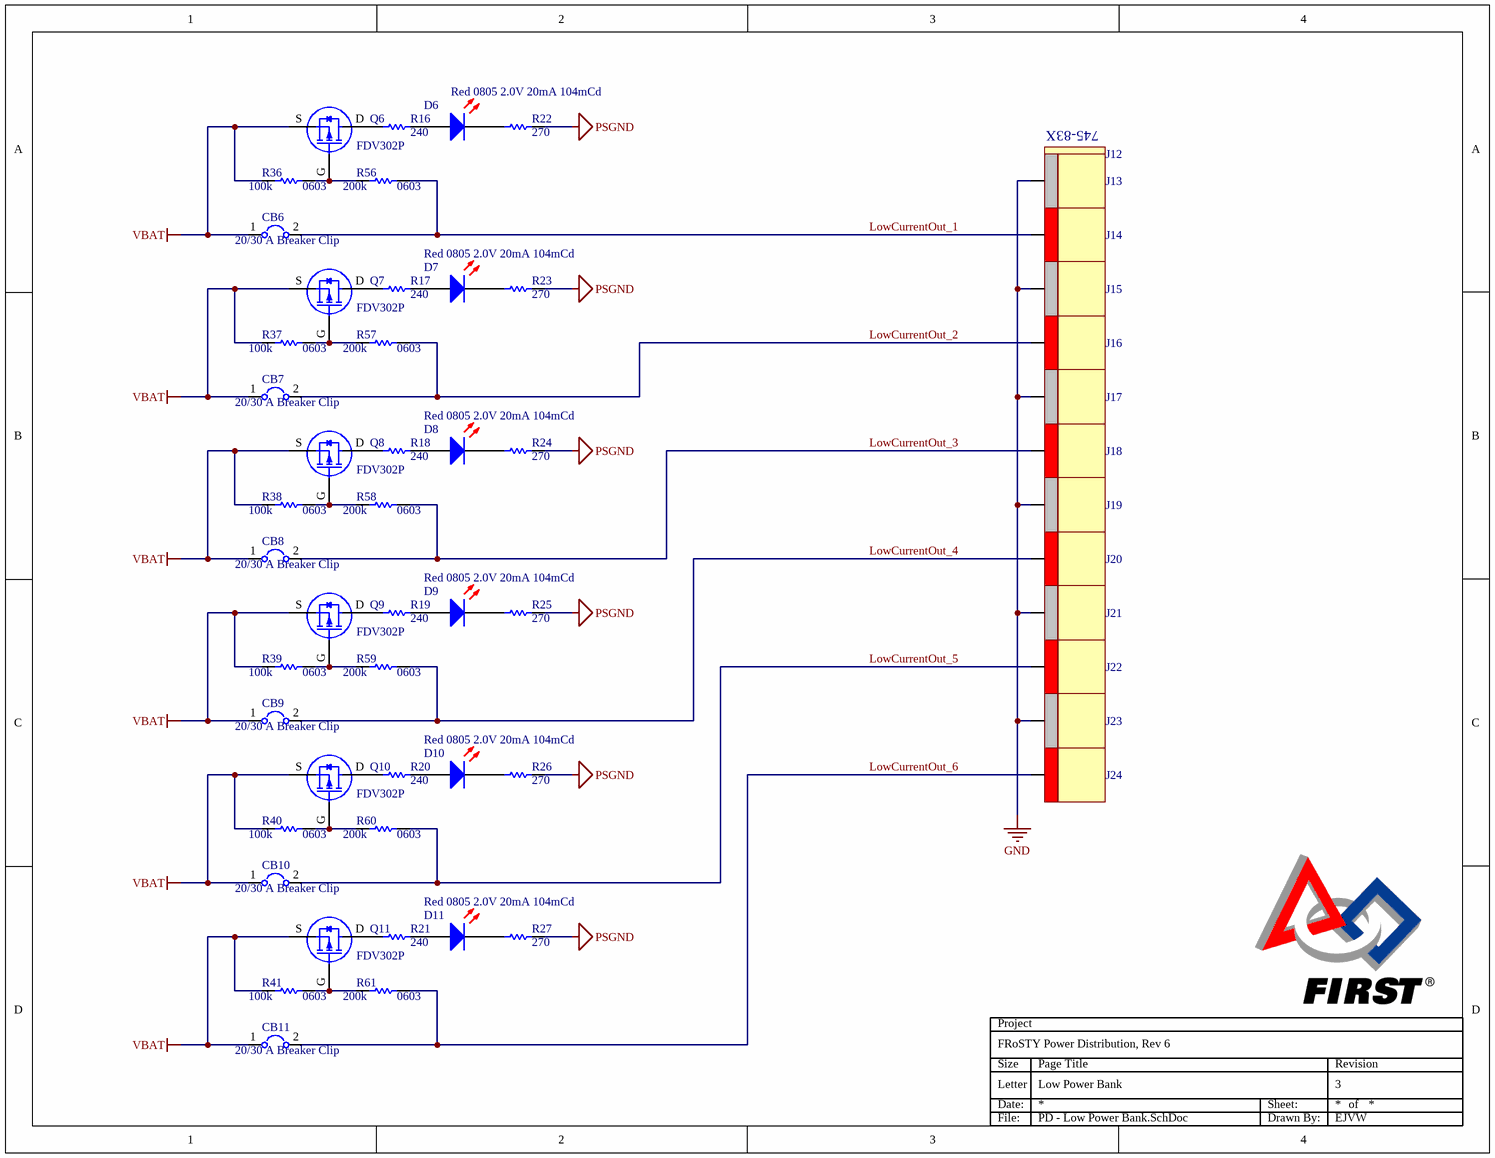
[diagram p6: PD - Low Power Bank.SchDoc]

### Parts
CB6  20/30 A Breaker Clip  [Keystone 3557-2]
CB7  20/30 A Breaker Clip  [Keystone 3557-2]
CB8  20/30 A Breaker Clip  [Keystone 3557-2]
CB9  20/30 A Breaker Clip  [Keystone 3557-2]
CB10  20/30 A Breaker Clip  [Keystone 3557-2]
CB11  20/30 A Breaker Clip  [Keystone 3557-2]
D6  Red 0805 2.0V 20mA 104mCd  [LED_0805 0.8 Red]
D7  Red 0805 2.0V 20mA 104mCd  [LED_0805 0.8 Red]
D8  Red 0805 2.0V 20mA 104mCd  [LED_0805 0.8 Red]
D9  Red 0805 2.0V 20mA 104mCd  [LED_0805 0.8 Red]
D10  Red 0805 2.0V 20mA 104mCd  [LED_0805 0.8 Red]
D11  Red 0805 2.0V 20mA 104mCd  [LED_0805 0.8 Red]
J12  745-300  [WAGO 745-300]  (value not drawn)
J13  745-831  [WAGO 745-83X]  (value not drawn)
J14  745-83X Red  [WAGO 745-83X Red]  (value not drawn)
J15  745-831  [WAGO 745-83X]  (value not drawn)
J16  745-83X Red  [WAGO 745-83X Red]  (value not drawn)
J17  745-831  [WAGO 745-83X]  (value not drawn)
J18  745-83X Red  [WAGO 745-83X Red]  (value not drawn)
J19  745-831  [WAGO 745-83X]  (value not drawn)
J20  745-83X Red  [WAGO 745-83X Red]  (value not drawn)
J21  745-831  [WAGO 745-83X]  (value not drawn)
J22  745-83X Red  [WAGO 745-83X Red]  (value not drawn)
J23  745-831  [WAGO 745-83X]  (value not drawn)
J24  745-83X Red  [WAGO 745-83X Red]  (value not drawn)
Q6  FDV302P  [SOT-23 FET]
Q7  FDV302P  [SOT-23 FET]
Q8  FDV302P  [SOT-23 FET]
Q9  FDV302P  [SOT-23 FET]
Q10  FDV302P  [SOT-23 FET]
Q11  FDV302P  [SOT-23 FET]
R16  value 240  [R1206_C]  (hidden comment: 240 ohm 1206 5%)
R17  value 240  [R1206_C]  (hidden comment: 240 ohm 1206 5%)
R18  value 240  [R1206_C]  (hidden comment: 240 ohm 1206 5%)
R19  value 240  [R1206_C]  (hidden comment: 240 ohm 1206 5%)
R20  value 240  [R1206_C]  (hidden comment: 240 ohm 1206 5%)
R21  value 240  [R1206_C]  (hidden comment: 240 ohm 1206 5%)
R22  value 270  [R1206_C]  (hidden comment: 270 ohm 1206 5%)
R23  value 270  [R1206_C]  (hidden comment: 270 ohm 1206 5%)
R24  value 270  [R1206_C]  (hidden comment: 270 ohm 1206 5%)
R25  value 270  [R1206_C]  (hidden comment: 270 ohm 1206 5%)
R26  value 270  [R1206_C]  (hidden comment: 270 ohm 1206 5%)
R27  value 270  [R1206_C]  (hidden comment: 270 ohm 1206 5%)
R36  value 100k  Footprint: 0603  [R0603_C]  (hidden comment: 100k ohm 0603 1%)
R37  value 100k  Footprint: 0603  [R0603_C]  (hidden comment: 100k ohm 0603 1%)
R38  value 100k  Footprint: 0603  [R0603_C]  (hidden comment: 100k ohm 0603 1%)
R39  value 100k  Footprint: 0603  [R0603_C]  (hidden comment: 100k ohm 0603 1%)
R40  value 100k  Footprint: 0603  [R0603_C]  (hidden comment: 100k ohm 0603 1%)
R41  value 100k  Footprint: 0603  [R0603_C]  (hidden comment: 100k ohm 0603 1%)
R56  value 200k  Footprint: 0603  [R0603_C]  (hidden comment: 200k ohm 0603 1%)
R57  value 200k  Footprint: 0603  [R0603_C]  (hidden comment: 200k ohm 0603 1%)
R58  value 200k  Footprint: 0603  [R0603_C]  (hidden comment: 200k ohm 0603 1%)
R59  value 200k  Footprint: 0603  [R0603_C]  (hidden comment: 200k ohm 0603 1%)
R60  value 200k  Footprint: 0603  [R0603_C]  (hidden comment: 200k ohm 0603 1%)
R61  value 200k  Footprint: 0603  [R0603_C]  (hidden comment: 200k ohm 0603 1%)

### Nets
GND: J13.1 J15.1 J17.1 J19.1 J21.1 J23.1
PSGND: R22.2 R23.2 R24.2 R25.2 R26.2 R27.2
VBAT: CB6.1 CB7.1 CB8.1 CB9.1 CB10.1 CB11.1 Q6.S Q7.S Q8.S Q9.S Q10.S Q11.S R36.1 R37.1 R38.1 R39.1 R40.1 R41.1
LowCurrentOut_1: CB6.2 J14.1 R56.2
LowCurrentOut_2: CB7.2 J16.1 R57.2
LowCurrentOut_3: CB8.2 J18.1 R58.2
LowCurrentOut_4: CB9.2 J20.1 R59.2
LowCurrentOut_5: CB10.2 J22.1 R60.2
LowCurrentOut_6: CB11.2 J24.1 R61.2
NetD6_A: D6.A R16.2
NetD6_K: D6.K R22.1
NetD7_A: D7.A R17.2
NetD7_K: D7.K R23.1
NetD8_A: D8.A R18.2
NetD8_K: D8.K R24.1
NetD9_A: D9.A R19.2
NetD9_K: D9.K R25.1
NetD10_A: D10.A R20.2
NetD10_K: D10.K R26.1
NetD11_A: D11.A R21.2
NetD11_K: D11.K R27.1
NetQ6_D: Q6.D R16.1
NetQ6_G: Q6.G R36.2 R56.1
NetQ7_D: Q7.D R17.1
NetQ7_G: Q7.G R37.2 R57.1
NetQ8_D: Q8.D R18.1
NetQ8_G: Q8.G R38.2 R58.1
NetQ9_D: Q9.D R19.1
NetQ9_G: Q9.G R39.2 R59.1
NetQ10_D: Q10.D R20.1
NetQ10_G: Q10.G R40.2 R60.1
NetQ11_D: Q11.D R21.1
NetQ11_G: Q11.G R41.2 R61.1

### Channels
LPB1: designators CB6=CB1#2 CB7=CB2 CB8=CB3 CB9=CB4 CB10=CB5 CB11=CB6 D6=D5 D7=D6 D8=D7 D9=D8 D10=D9 D11=D10 J12=J10 J13=J11 J14=J12 J15=J13 J16=J14 J17=J15 J18=J16 J19=J17 J20=J18 J21=J19 J22=J20 J23=J21 J24=J22 Q6=Q5 Q7=Q6 Q8=Q7 Q9=Q8 Q10=Q9 Q11=Q10 R16=R9 R17=R11 R18=R13 R19=R15 R20=R17 R21=R19 R22=R10 R23=R12 R24=R14 R25=R16 R26=R18 R27=R20 R36=R26 R37=R27 R38=R28#2 R39=R29#2 R40=R30#2 R41=R31#2 R56=R96 R57=R97 R58=R98 R59=R99 R60=R100 R61=R101
LPB2: designators CB6=CB24 CB7=CB23 CB8=CB22 CB9=CB21 CB10=CB20 CB11=CB19 D6=D27 D7=D26 D8=D25 D9=D24 D10=D23 D11=D22 J12=J49 J13=J48 J14=J47 J15=J46 J16=J45 J17=J44 J18=J43 J19=J42 J20=J41 J21=J40 J22=J39 J23=J38 J24=J37 Q6=Q19 Q7=Q18 Q8=Q17 Q9=Q16 Q10=Q15 Q11=Q14 R16=R81 R17=R79 R18=R77 R19=R75 R20=R73 R21=R71 R22=R80 R23=R78 R24=R76 R25=R74 R26=R72 R27=R70 R36=R60 R37=R59 R38=R58 R39=R57 R40=R56 R41=R55 R56=R90 R57=R91 R58=R92 R59=R93 R60=R94 R61=R95

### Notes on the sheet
- (near J12) 745-83X

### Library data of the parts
CB6-CB11 = KeyElco 3557-2: Standard Automotive Blade Fuse Clips & Holder - Edge; MFG: Keystone Electronics; MFG_PN: 3557-2; I hold (A): Per Breaker; I max (A): 30 A
D6-D11 = LS R976-NR-1-0-20-R18: as D2 on sheet PD - High Power Bank
J12 = Wago 745-300: Wago 745-83X End Plate
J13 J15 J17 J19 J21 J23 = Wago 745-83X Grey: Current Rating: 32 A
J14 J16 J18 J20 J22 J24 = Wago 745-83X Red: Current Rating: 32 A
Q6-Q11 = FDV302P: as Q2 on sheet PD - High Power Bank
R16-R21 = 240 ohm 1206 5%: as R8 on sheet PD - High Power Bank
R22-R27 = 270 ohm 1206 5%: as R12 on sheet PD - High Power Bank
R36-R41 = 100k ohm 0603 1%: as R62#1 on sheet PD - power supplies
R56-R61 = 200k ohm 0603 1%: as R52 on sheet PD - High Power Bank

## Sheet Title.SchDoc
size Letter; SheetNumber: 1
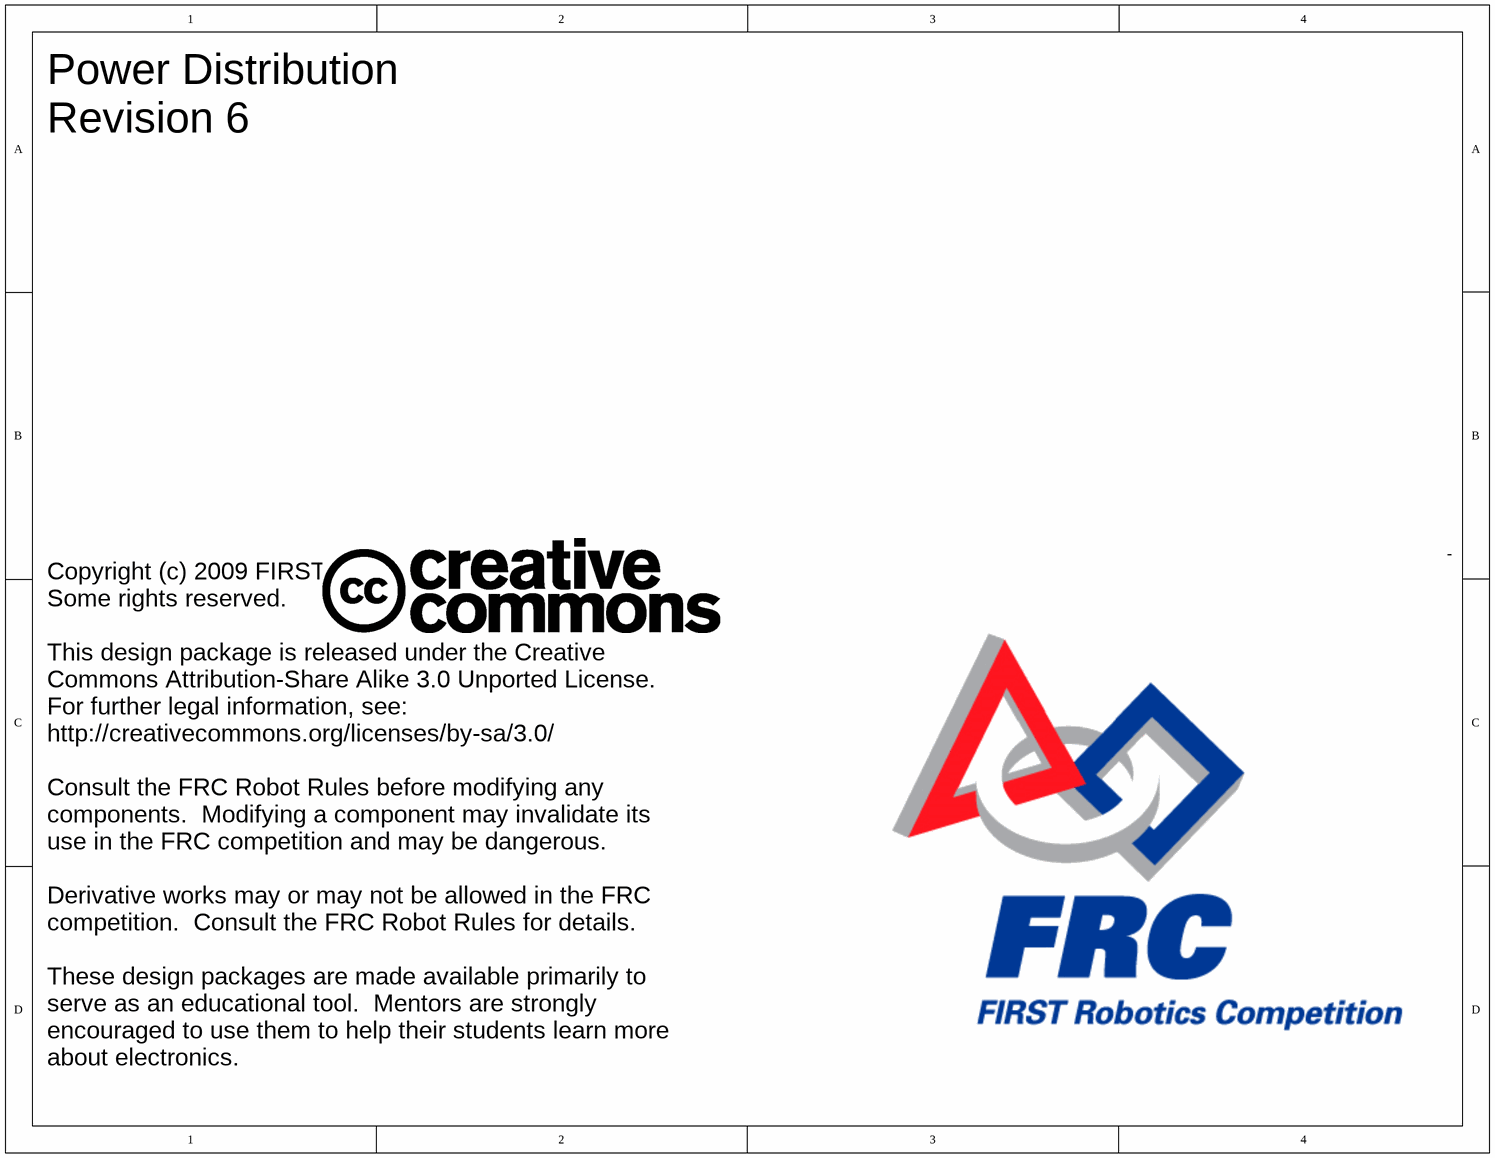
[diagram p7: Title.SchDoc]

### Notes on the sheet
- Power Distribution
  Revision 6
- Copyright (c) 2009 FIRST
  Some rights reserved.
  This design package is released under the Creative Commons Attribution-Share Alike 3.0 Unported License.  For further legal information, see:
  http://creativecommons.org/licenses/by-sa/3.0/
  Consult the FRC Robot Rules before modifying any components.  Modifying a component may invalidate its use in the FRC competition and may be dangerous.
  Derivative works may or may not be allowed in the FRC competition.  Consult the FRC Robot Rules for details.
  These design packages are made available primarily to serve as an educational tool.  Mentors are strongly encouraged to use them to help their students learn more about electronics.

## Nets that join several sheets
GND: PD - power supplies (J2#1.PAD Q13.D), HPB2 (J29.1 J31.1 J33.1 J35.1), HPB1 (J1#2.1 J4.1 J6.1 J8.1), LPB1 (6 pins), LPB2 (6 pins)
PSGND: PD - power supplies (9 pins), 24V_1.5A Supply (14 pins), 5V_3A Supply (8 pins), 12V_2A Supply (13 pins), HPB2 (D18#2.K D19.K D20#2.K D21.K), HPB1 (D1#2.K D2.K D3.K D4.K), LPB1 (6 pins), LPB2 (6 pins)
VBAT: PD - power supplies (CB1#1.2 CB14#1.2 J1#1.PAD R62#1.2), HPB2 (12 pins), HPB1 (12 pins), LPB1 (18 pins), LPB2 (18 pins)
NetC4_2: 24V_1.5A Supply (C4.2 C20.2 L1.2 R1#1.1), 5V_3A Supply (C8.2 C9.2 U2.7), 12V_2A Supply (C16.2 C19.2 L3.2 R42.2)
NetC11_2: 24V_1.5A Supply (C21.+ L4.2), 5V_3A Supply (C11.2 C12.+ L2.2 R28#1.2), 12V_2A Supply (C22.+ L5.2)
NetR2#1_2: 24V_1.5A Supply (R2#1.2 U1.7), 12V_2A Supply (R43.2 U3.7)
